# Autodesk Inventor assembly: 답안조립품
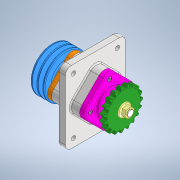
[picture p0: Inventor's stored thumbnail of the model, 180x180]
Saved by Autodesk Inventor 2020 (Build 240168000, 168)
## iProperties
Created: 2021-07
Part Number: 답안조립품
Document SubType Name: Assembly
Designer: Owner
Author: Owner
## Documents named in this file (16)
- C:\Users\Owner\Desktop\710707V1020\답안조립품.iam
- C:\Users\Owner\Desktop\710707V1020\본체.ipt
- C:\Users\Owner\Desktop\710707V1020\M16 너트.ipt
- C:\Users\Owner\Desktop\710707V1020\V-벨트풀리.ipt
- C:\Users\Owner\Desktop\710707V1020\멈춤나사 M4.ipt
- C:\Users\Owner\Desktop\710707V1020\베어링 6206.ipt
- C:\Users\Owner\Desktop\710707V1020\볼트 M6.ipt
- C:\Users\Owner\Desktop\710707V1020\부시.ipt
- C:\Users\Owner\Desktop\710707V1020\오일실 30x42x8.ipt
- C:\Users\Owner\Desktop\710707V1020\오일실 30x45x8.ipt
- C:\Users\Owner\Desktop\710707V1020\체인 스프로킷.ipt
- C:\Users\Owner\Desktop\710707V1020\축.ipt
- C:\Users\Owner\Desktop\710707V1020\커버A.ipt
- C:\Users\Owner\Desktop\710707V1020\커버B.ipt
- C:\Users\Owner\Desktop\710707V1020\키 6x6x18.ipt
- C:\Users\Owner\Desktop\710707V1020\키 6x6x20.ipt
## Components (3 placed, 2 different names)
1. M16 너트:1 — 각도:3
2. V-벨트풀리:1 — 각도:2
3. M16 너트:2 — 각도:4
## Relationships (3: Angle 3)
- 각도:2 [Angle]: V-벨트풀리:1
- 각도:3 [Angle]: M16 너트:1
- 각도:4 [Angle]: M16 너트:2
